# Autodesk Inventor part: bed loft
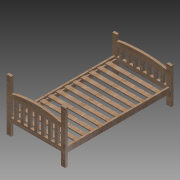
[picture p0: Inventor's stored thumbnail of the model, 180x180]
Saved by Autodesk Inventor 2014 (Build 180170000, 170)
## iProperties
Created: 2013-07
Part Number: bed loft
Material: Wood (Oak)
Document SubType Name: Modeling
Designer: Patrick Rice
Density: 0.76 g/cm^3
Appearance: Red Oak - Natural
Author: Patrick Rice
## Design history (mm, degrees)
sketch "Sketch1" dims "d17" = 25.4
  geometry: L1 (-970.588, 298.363)-(-888.038, 298.363); L2 (-888.038, 298.363)-(-888.038, -362.037); L3 (-888.038, -362.037)-(-970.588, -362.037); L4 (-970.588, -362.037)-(-970.588, 298.363); L5 (39.062, -362.037)-(121.612, -362.037); L6 (121.612, -362.037)-(121.612, 298.363); L7 (121.612, 298.363)-(39.062, 298.363); L8 (39.062, 298.363)-(39.062, -362.037); L9 (-888.038, -133.437)-(39.062, -133.437); L10 (39.062, -133.437)-(39.062, -57.237); L11 (39.062, -57.237)-(-888.038, -57.237); L12 (-888.038, -57.237)-(-888.038, -133.437); L13 (-888.038, 120.563)-(39.062, 120.563); L14 (39.062, 120.563)-(39.062, 196.763); L15 (39.062, 196.763)-(-888.038, 196.763); L16 (-888.038, 196.763)-(-888.038, 120.563); L17 (-888.038, 196.763)-(-424.488, 279.193); L18 (-424.488, 279.193)-(39.062, 196.763); L19 (-837.238, 120.563)-(-786.438, 120.563); L20 (-786.438, 120.563)-(-786.438, -57.237); L21 (-786.438, -57.237)-(-837.238, -57.237); L22 (-837.238, -57.237)-(-837.238, 120.563); L23 (-710.238, -57.237)-(-710.238, 120.563); L24 (-659.438, -57.237)-(-710.238, -57.237); L25 (-659.438, 120.563)-(-659.438, -57.237); L26 (-710.238, 120.563)-(-659.438, 120.563); L27 (-583.238, -57.237)-(-583.238, 120.563); L28 (-532.438, -57.237)-(-583.238, -57.237); L29 (-532.438, 120.563)-(-532.438, -57.237); L30 (-583.238, 120.563)-(-532.438, 120.563); L31 (-456.238, -57.237)-(-456.238, 120.563); L32 (-405.438, -57.237)-(-456.238, -57.237); L33 (-405.438, 120.563)-(-405.438, -57.237); L34 (-456.238, 120.563)-(-405.438, 120.563); L35 (-329.238, -57.237)-(-329.238, 120.563); L36 (-278.438, -57.237)-(-329.238, -57.237); L37 (-278.438, 120.563)-(-278.438, -57.237); L38 (-329.238, 120.563)-(-278.438, 120.563); L39 (-202.238, -57.237)-(-202.238, 120.563); L40 (-151.438, -57.237)-(-202.238, -57.237); L41 (-151.438, 120.563)-(-151.438, -57.237); L42 (-202.238, 120.563)-(-151.438, 120.563); L43 (-75.238, -57.237)-(-75.238, 120.563); L44 (-24.438, -57.237)-(-75.238, -57.237); L45 (-24.438, 120.563)-(-24.438, -57.237); L46 (-75.238, 120.563)-(-24.438, 120.563); 1 further point
  constraints: 88 end point, 11 equal length, 6 horizontal, 6 point on line, 5 perpendicular, 1 collinear, 51 other
  dimensions: "d0" = 660.4 distance of L3.end L1.start; "d1" = 82.55 distance of L1.start L1.end; "d2" = 82.55 distance of L6.end L7.end; "d3" = 660.4 distance of L5.end L6.end; "d5" = 1092.2 distance between parallel lines of L6 L4; "d6" = 228.6 distance between parallel lines of L3 L9; "d7" = 76.2 distance between parallel lines of L9 L11; "d8" = 76.2 distance between parallel lines of L13 L15; "d9" = 177.8 distance between parallel lines of L11 L13; "d10" = 50.8 distance between parallel lines of L22 L2; "d11" = 50.8 distance between parallel lines of L20 L22; "d14" = 127 distance of L19.start L23.end
extrude "Extrusion1" new body sketch "Sketch1" distance "d19" = 44.45; taper "d20" = 0 deg
sketch "Sketch2"
  geometry: L1 (-970.588, 298.363)-(-970.588, -362.037) reference; L2 (-970.588, -362.037)-(-888.038, -362.037) reference; L3 (121.612, -362.037)-(121.612, 298.363) reference; L4 (-945.188, -57.237)-(-913.438, -57.237); L5 (-913.438, -57.237)-(-913.438, -158.837); L6 (-913.438, -158.837)-(-945.188, -158.837); L7 (-945.188, -158.837)-(-945.188, -57.237); L8 (64.462, -57.237)-(96.212, -57.237); L9 (96.212, -57.237)-(96.212, -158.837); L10 (96.212, -158.837)-(64.462, -158.837); L11 (64.462, -158.837)-(64.462, -57.237); L12 (-913.438, -158.837)-(-888.038, -158.837); L13 (-888.038, -158.837)-(-888.038, -95.337); L14 (-888.038, -95.337)-(-913.438, -95.337); L15 (-913.438, -95.337)-(-913.438, -158.837); L16 (64.462, -158.837)-(39.062, -158.837); L17 (39.062, -158.837)-(39.062, -95.337); L18 (39.062, -95.337)-(64.462, -95.337); L19 (64.462, -95.337)-(64.462, -158.837); 1 further point
  constraints: 32 end point, 8 parallel, 4 horizontal, 4 perpendicular, 1 collinear
  dimensions: "d21" = 203.2 distance between parallel lines of L2 L6; "d22" = 101.6 distance of L6.end L4.start; "d23" = 31.75 distance of L4.start L4.end; "d24" = 31.75 distance of L8.start L8.end; "d25" = 101.6 distance of L8.end L9.end; "d26" = 25.4 distance between parallel lines of L9 L3; "d27" = 25.4 distance between parallel lines of L1 L7; "d55" = 63.5 distance of L12.end L13.end; "d56" = 25.4 distance of L13.end L14.end; "d57" = 25.4 distance of L17.end L18.end; "d58" = 63.5 distance of L16.end L17.end
extrude "Extrusion2" join sketch "Sketch2" distance "d28" = 1917.7; taper "d29" = 0 deg
sketch "Sketch3" dims "d51" = 25.4
  geometry: L1 (-945.188, -57.237)-(-945.188, -158.837) reference; L2 (-945.188, -158.837)-(-888.038, -158.837) reference; L3 (-970.588, -362.037)-(-888.038, -362.037); L4 (-888.038, -362.037)-(-888.038, 603.163); L5 (-888.038, 603.163)-(-970.588, 603.163); L6 (-970.588, 603.163)-(-970.588, -362.037); L7 (-888.038, -133.437)-(39.062, -133.437); L8 (39.062, -133.437)-(39.062, -57.237); L9 (39.062, -57.237)-(-888.038, -57.237); L10 (-888.038, -57.237)-(-888.038, -133.437); L11 (39.062, -362.037)-(121.612, -362.037); L12 (121.612, -362.037)-(121.612, 603.163); L13 (121.612, 603.163)-(39.062, 603.163); L14 (39.062, 603.163)-(39.062, -362.037); L15 (-888.038, 323.763)-(39.062, 323.763); L16 (39.062, 323.763)-(39.062, 247.563); L17 (39.062, 247.563)-(-888.038, 247.563); L18 (-888.038, 247.563)-(-888.038, 323.763); L19 (-888.038, 323.763)-(-443.236, 452.14); L20 (-443.236, 452.14)-(39.062, 323.763); L21 (-837.238, -57.237)-(-786.438, -57.237); L22 (-786.438, -57.237)-(-786.438, 247.563); L23 (-786.438, 247.563)-(-837.238, 247.563); L24 (-837.238, 247.563)-(-837.238, -57.237); L25 (-659.438, 247.563)-(-710.238, 247.563); L26 (-659.438, -57.237)-(-659.438, 247.563); L27 (-710.238, 247.563)-(-710.238, -57.237); L28 (-710.238, -57.237)-(-659.438, -57.237); L29 (-532.438, 247.563)-(-583.238, 247.563); L30 (-532.438, -57.237)-(-532.438, 247.563); L31 (-583.238, 247.563)-(-583.238, -57.237); L32 (-583.238, -57.237)-(-532.438, -57.237); L33 (-405.438, 247.563)-(-456.238, 247.563); L34 (-405.438, -57.237)-(-405.438, 247.563); L35 (-456.238, 247.563)-(-456.238, -57.237); L36 (-456.238, -57.237)-(-405.438, -57.237); L37 (-278.438, 247.563)-(-329.238, 247.563); L38 (-278.438, -57.237)-(-278.438, 247.563); L39 (-329.238, 247.563)-(-329.238, -57.237); L40 (-329.238, -57.237)-(-278.438, -57.237); L41 (-151.438, 247.563)-(-202.238, 247.563); L42 (-151.438, -57.237)-(-151.438, 247.563); L43 (-202.238, 247.563)-(-202.238, -57.237); L44 (-202.238, -57.237)-(-151.438, -57.237); L45 (-24.438, 247.563)-(-75.238, 247.563); L46 (-24.438, -57.237)-(-24.438, 247.563); L47 (-75.238, 247.563)-(-75.238, -57.237); L48 (-75.238, -57.237)-(-24.438, -57.237); 2 further points
  constraints: 88 end point, 10 parallel, 6 horizontal, 5 perpendicular, 5 point on line, 2 collinear, 51 other
  dimensions: "d30" = 203.2 distance between parallel lines of L3 L2; "d31" = 82.55 distance of L4.end L5.end; "d32" = 25.4 distance between parallel lines of L6 L1; "d33" = 965.2 distance of L5.end L3.start; "d35" = 82.55 distance of L12.end L13.end; "d36" = 965.2 distance of L11.end L12.end; "d37" = 76.2 distance between parallel lines of L7 L9; "d38" = 228.6 distance between parallel lines of L3 L7; "d41" = 1092.2 distance between parallel lines of L12 L6; "d42" = 76.2 distance between parallel lines of L17 L15; "d43" = 304.8 distance between parallel lines of L9 L17; "d44" = 50.8 distance from line of L22 L23.end; "d45" = 50.8 distance between parallel lines of L4 L24; "d48" = 127 distance of L22.end L25.start
extrude "Extrusion3" join sketch "Sketch3" distance "d53" = 44.45; taper "d54" = 0 deg
sketch "Sketch5" dims "d68" = 25.4
  geometry: L1 (1917.7, 0)-(0, 0) reference; L2 (1917.7, 38.1)-(0, 38.1) reference; L3 (0, 0)-(0, 38.1) reference; L4 (50.8, 0)-(127, 0); L5 (127, 0)-(127, 19.05); L6 (127, 19.05)-(50.8, 19.05); L7 (50.8, 19.05)-(50.8, 0); L8 (203.2, 0)-(279.4, 0); L9 (279.4, 0)-(279.4, 19.05); L10 (279.4, 19.05)-(203.2, 19.05); L11 (203.2, 19.05)-(203.2, 0); L12 (355.6, 0)-(431.8, 0); L13 (431.8, 0)-(431.8, 19.05); L14 (431.8, 19.05)-(355.6, 19.05); L15 (355.6, 19.05)-(355.6, 0); L16 (508, 0)-(584.2, 0); L17 (584.2, 0)-(584.2, 19.05); L18 (584.2, 19.05)-(508, 19.05); L19 (508, 19.05)-(508, 0); L20 (660.4, 0)-(736.6, 0); L21 (736.6, 0)-(736.6, 19.05); L22 (736.6, 19.05)-(660.4, 19.05); L23 (660.4, 19.05)-(660.4, 0); L24 (812.8, 0)-(889, 0); L25 (889, 0)-(889, 19.05); L26 (889, 19.05)-(812.8, 19.05); L27 (812.8, 19.05)-(812.8, 0); L28 (965.2, 0)-(1041.4, 0); L29 (1041.4, 0)-(1041.4, 19.05); L30 (1041.4, 19.05)-(965.2, 19.05); L31 (965.2, 19.05)-(965.2, 0); L32 (1117.6, 0)-(1193.8, 0); L33 (1193.8, 0)-(1193.8, 19.05); L34 (1193.8, 19.05)-(1117.6, 19.05); L35 (1117.6, 19.05)-(1117.6, 0); L36 (1270, 0)-(1346.2, 0); L37 (1346.2, 0)-(1346.2, 19.05); L38 (1346.2, 19.05)-(1270, 19.05); L39 (1270, 19.05)-(1270, 0); L40 (1422.4, 0)-(1498.6, 0); L41 (1498.6, 0)-(1498.6, 19.05); L42 (1498.6, 19.05)-(1422.4, 19.05); L43 (1422.4, 19.05)-(1422.4, 0); L44 (1574.8, 0)-(1651, 0); L45 (1651, 0)-(1651, 19.05); L46 (1651, 19.05)-(1574.8, 19.05); L47 (1574.8, 19.05)-(1574.8, 0); L48 (1727.2, 0)-(1803.4, 0); L49 (1803.4, 0)-(1803.4, 19.05); L50 (1803.4, 19.05)-(1727.2, 19.05); L51 (1727.2, 19.05)-(1727.2, 0); 1 further point
  constraints: 96 end point, 2 horizontal, 2 parallel, 1 perpendicular, 1 point on line, 88 other
  dimensions: "d60" = 19.05 distance of L4.end L5.end; "d61" = 76.2 distance of L5.end L6.end; "d62" = 50.8 distance between parallel lines of L7 L3; "d65" = 152.4 distance of L4.start L8.start
extrude "Extrusion4" join sketch "Sketch5" stored distance "d70" = 44.45; taper "d71" = 0 deg
body "Solid1"
